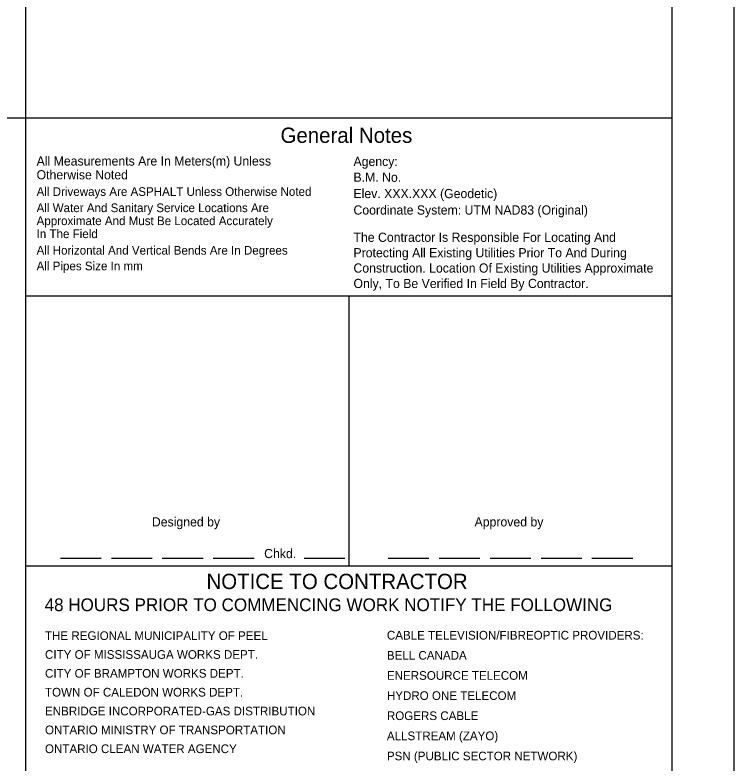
# Model space of a CAD drawing. Extents: x 613360 to 613780, y 4825621 to 4825911.
# Drawn here: x 613709.7 to 613780.3, y 4825692.8 to 4825766.2 of the extents above; entities that cross this region are included whole.
import ezdxf

# ---------------------------------------------------------------- set-up
doc = ezdxf.new("R2010")
doc.units = 0
for name, color, linetype in [('G-ANNO-STMP', 7, 'Continuous'), ('G-ANNO-TEXT', 7, 'Continuous'), ('G-TTLB-OTLN', 7, 'Continuous'), ('G-TTLB-OTLN-PB', 7, 'Continuous')]:
    doc.layers.add(name, color=color, linetype=linetype)

msp = doc.modelspace()

# ---------------------------------------------------------------- linework, layer by layer
at = {"layer": 'G-ANNO-STMP'}
for p, q in [((613714.165, 4825712.893), (613718.165, 4825712.892)), ((613719.165, 4825712.892), (613723.165, 4825712.892)), ((613724.165, 4825712.892), (613728.165, 4825712.892)), ((613729.165, 4825712.892), (613733.165, 4825712.892)), ((613738.073, 4825712.892), (613742.073, 4825712.892)), ((613746.328, 4825712.892), (613750.328, 4825712.892)), ((613751.328, 4825712.892), (613755.328, 4825712.892)), ((613756.328, 4825712.892), (613760.328, 4825712.892)), ((613761.328, 4825712.892), (613765.328, 4825712.892)), ((613766.328, 4825712.892), (613770.328, 4825712.892))]:
    msp.add_line(p, q, dxfattribs=at)
at = {"layer": 'G-TTLB-OTLN'}
for p, q in [((613710.777, 4825623.508), (613710.777, 4825815.929)), ((613380.085, 4825756.108), (613774.178, 4825756.108)), ((613774.178, 4825738.607), (613710.777, 4825738.607)), ((613742.478, 4825738.607), (613742.478, 4825712.108)), ((613774.178, 4825712.108), (613710.777, 4825712.108))]:
    msp.add_line(p, q, dxfattribs=at)
msp.add_lwpolyline([(613380.085, 4825892.077), (613774.178, 4825892.077), (613774.178, 4825623.508), (613380.085, 4825623.508)], close=True, dxfattribs=at)
at = {"layer": 'G-TTLB-OTLN-PB'}
msp.add_lwpolyline([(613359.578, 4825620.908), (613780.27, 4825620.908), (613780.27, 4825894.677), (613359.578, 4825894.677)], close=True, dxfattribs=at)

# ---------------------------------------------------------------- texts
at = {"layer": 'G-ANNO-STMP'}
for s, p in [('Designed by', (613723.139, 4825715.999)), ('Approved by', (613754.805, 4825715.999)), ('Chkd.', (613734.158, 4825712.892))]:
    msp.add_text(s, height=0.9, dxfattribs=at).set_placement(p)
at = {"layer": 'G-ANNO-TEXT'}
for s, height, p in [('General Notes', 1.5, (613735.763, 4825753.635)), ('All Measurements Are In Meters(m) Unless ', 0.9, (613711.826, 4825751.407)), ('Otherwise Noted', 0.9, (613711.826, 4825750.057)), ('All Driveways Are ASPHALT Unless Otherwise Noted', 0.85, (613711.826, 4825748.433)), ('All Water And Sanitary Service Locations Are ', 0.85, (613711.826, 4825746.84)), ('Approximate And Must Be Located Accurately ', 0.85, (613711.826, 4825745.565)), ('In The Field ', 0.85, (613711.826, 4825744.29)), ('All Horizontal And Vertical Bends Are In Degrees', 0.85, (613711.826, 4825742.671))]:
    msp.add_text(s, height=height, rotation=360, dxfattribs=at).set_placement(p)
for s, height, p in [('Agency: ', 0.9, (613742.923, 4825751.368)), ('B.M. No. ', 0.9, (613742.923, 4825749.815)), ('Elev. XXX.XXX (Geodetic)', 0.9, (613742.923, 4825748.215)), ('Coordinate System: UTM NAD83 (Original)', 0.9, (613742.923, 4825746.601)), ('The Contractor Is Responsible For Locating And ', 0.9, (613742.923, 4825743.923)), ('Protecting All Existing Utilities Prior To And During ', 0.9, (613742.923, 4825742.407)), ('All Pipes Size In mm', 0.85, (613711.826, 4825741.135)), ('Construction. Location Of Existing Utilities Approximate ', 0.9, (613742.923, 4825740.907)), ('Only, To Be Verified In Field By Contractor.', 0.9, (613742.923, 4825739.391)), ('NOTICE TO CONTRACTOR', 1.5, (613728.497, 4825709.856)), ('48 HOURS PRIOR TO COMMENCING WORK NOTIFY THE FOLLOWING', 1.25, (613712.613, 4825707.688)), ('THE REGIONAL MUNICIPALITY OF PEEL', 0.85, (613712.651, 4825704.86)), ('CABLE TELEVISION/FIBREOPTIC PROVIDERS:', 0.85, (613746.202, 4825704.902)), ('CITY OF MISSISSAUGA WORKS DEPT.', 0.85, (613712.651, 4825703.01)), ('BELL CANADA', 0.85, (613746.202, 4825702.927)), ('CITY OF BRAMPTON WORKS DEPT.', 0.85, (613712.651, 4825701.16)), ('ENERSOURCE TELECOM', 0.85, (613746.202, 4825700.952)), ('TOWN OF CALEDON WORKS DEPT.', 0.85, (613712.651, 4825699.31)), ('HYDRO ONE TELECOM', 0.85, (613746.202, 4825698.977)), ('ENBRIDGE INCORPORATED-GAS DISTRIBUTION', 0.85, (613712.651, 4825697.46)), ('ROGERS CABLE', 0.85, (613746.202, 4825697.002)), ('ONTARIO MINISTRY OF TRANSPORTATION', 0.85, (613712.651, 4825695.61)), ('ALLSTREAM (ZAYO)', 0.85, (613746.202, 4825695.027)), ('ONTARIO CLEAN WATER AGENCY', 0.85, (613712.651, 4825693.76)), ('PSN (PUBLIC SECTOR NETWORK)', 0.85, (613746.202, 4825693.052))]:
    msp.add_text(s, height=height, dxfattribs=at).set_placement(p)

doc.saveas('drawing.dxf')
